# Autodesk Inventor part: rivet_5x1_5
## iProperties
Created: 2011-01
Part Number: rivet_5x1_5
Document SubType Name: Modeling
Designer: eric
Density: 1 g/cm^3
Mass: 0.0865896 g
Surface Area: 1.78153 cm^2
Volume: 0.0865896 cm^3
Author: eric
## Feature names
1. Base1
